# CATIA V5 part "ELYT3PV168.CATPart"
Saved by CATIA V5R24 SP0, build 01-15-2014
Part number: ELYT3PV168
Material "ZAMA": density 6700 kg/m3
Material "ZAMA": density 6700 kg/m3
Bounding box of the stored display mesh (mm): x -59 to 27.5, y 0 to 1680, z 0 to 1500
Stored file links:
  \\mnsrv021stg\Common\AREA TECNICA\Documenti\3D sito\Componenti risolti\ELYT3PV168.CATPart
  Z:\commesse\Novellini\Serie Zephiros\BH01S66\ID_18668_00.CATPart
  Z:\commesse\Novellini\Prove\Tabelladiprogetto1.txt
  Z:\commesse\Novellini\Prove\Tabelladiprogetto2.xls
  C:\Users\n.rebecchi\Desktop\Scambio\ID_35222_00.xls
  Z:\3D sito\BH02A.xlsx
  \\MNSRV021STG\Common\AREA TECNICA\Documenti\3D sito\BOX\ZEPHIROS\BH02A\BH02A.xls
  Z:\3D sito\ZEPHIROS\BH022P\BH022P.xls
  C:\Docisland\DocIsland\catia_workdir\diclient\N.REBECCHI\ID_21111_03.CATPart
  C:\Docisland\DocIsland\catia_workdir\diclient\N.REBECCHI\ID_29051_00.CATPart
  U:\AREA TECNICA\Documenti\3D sito\BOX\ZEPHYROS\ZEPHYR3P\BH013P.xls
  \\mnsrv021stg\Common\AREA TECNICA\Documenti\3D sito\BOX\ELYT\ZEPHYR3P\ELYT3PV.xls
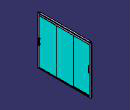
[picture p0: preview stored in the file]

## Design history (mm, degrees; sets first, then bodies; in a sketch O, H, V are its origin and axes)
Parameters
  `Larghezza anta` = 541 mm
  `MISURA NOMINALE` = 1680 mm
  PartNumber = "ELYT3PV168"
  `Lunghezza binario` = 1586 mm
Pad1: profile Sketch3.L13, length 1441, opposite side length -21
Solid1: solid without history
Solid2: solid without history
Pad2: profile Sketch3.L6, length 1441, opposite side length -21
Sketch1 on xy-plane, origin (0, 0, 0), H (1, 0, 0), V (0, 1, 0)
  axis line L1 (84.1025, 840) -> (-125.0839, 840)
  point P3 (-18.5, 0)
  point P4 (-18.5, 52.3)
  point P5 (0, 50.8)
  point P6 (-1.5, 52.3)
  point P8 (0, 1.5)
  point P9 (-1.5, 0)
  line L2 (0, 50.8) -> (0, 1.5)
  line L3 (-1.5, 0) -> (-32.75, 0)
  line L4 (-18.5, 1.5) -> (-18.5, 52.3)
  line L5 (-18.5, 52.3) -> (-1.5, 52.3)
  arc A1 centre (-1.5, 50.8) radius 1.5 from (0, 50.8) to (-1.5, 52.3) ccw
  arc A2 centre (-1.5, 1.5) radius 1.5 from (0, 1.5) to (-1.5, 0) cw
  line L6 (-18.5, 1.5) -> (-32.75, 1.5)
  point P11 (-32.75, 1.5)
  arc A3 centre (-32.75, 0.75) radius 0.75 from (-32.75, 1.5) to (-32.75, 0) ccw
  point P13 (-32.75, 0)
  point P14 (-18.5, 1.5)
  point P15 (-3, 1307.7)
  construction line L7 through (-1555.4, 0) direction (-1, 0)
  construction line L8 through (-1255.4, 0) direction (0, 1)
  point P16 (-18.5, 1680)
  point P17 (-18.5, 1627.7)
  point P18 (0, 1629.2)
  point P19 (-1.5, 1627.7)
  point P21 (0, 1678.5)
  point P22 (-1.5, 1680)
  point P24 (-32.75, 1678.5)
  point P26 (-32.75, 1680)
  point P27 (-18.5, 1678.5)
  line L9 (0, 1629.2) -> (0, 1678.5)
  line L10 (-1.5, 1680) -> (-32.75, 1680)
  line L11 (-18.5, 1678.5) -> (-18.5, 1629.1)
  line L12 (-52, 1627.7) -> (-1.5, 1627.7)
  arc A4 centre (-1.5, 1629.2) radius 1.5 from (0, 1629.2) to (-1.5, 1627.7) cw
  arc A5 centre (-1.5, 1678.5) radius 1.5 from (0, 1678.5) to (-1.5, 1680) ccw
  line L13 (-18.5, 1678.5) -> (-32.75, 1678.5)
  arc A6 centre (-32.75, 1679.25) radius 0.75 from (-32.75, 1678.5) to (-32.75, 1680) cw
  line L14 (-52, 1627.7) -> (-52, 1638.2)
  line L15 (-52, 1638.2) -> (-37, 1638.2)
  line L16 (-37, 1638.2) -> (-37, 1629.1)
  line L17 (-37, 1629.1) -> (-18.5, 1629.1)
  length L5 = 17
  radius A1 = 1.5
  distance L6 L3 = 1.5
  distance L4 A3 = 15
  distance L5 L3 = 52.3
  distance L2 L4 = 18.5
  radius A2 = 1.5
  distance L10 L3 = 1680 {= `MISURA NOMINALE`}
  distance L9 L14 = 52
  length L15 = 15
  distance L12 L17 = 1.4
  distance L15 L12 = 10.5
  tangency: A1 L2, A3 L3, A3 L6, L2 A2, A2 L3
  coincidence: P3 L3, P17 L11, P17 L12, L2 V, L3 L7, L3 H
  symmetry: P3 P16 L1, P4 P17 L1, P5 P18 L1, P6 P19 L1, P8 P21 L1, P9 P22 L1, P11 P24 L1, P13 P26 L1, P14 P27 L1, L2 L9 L1, L3 L10 L1, L4 L11 L1, L5 L12 L1, A1 A4 L1, A2 A5 L1, L6 L13 L1, A3 A6 L1
  vertical: L16 V
Pad3: profile Sketch1, direction (0, 0, 1), length 1500
Body1 "Telaio" (main body)
  Sketch2 on face of Pad3 from Sketch1.L5, origin (0, 52.3, 0), H (-1, 0, 0), V (0, 0, -1)
    point P1 (-1, -1500)
    line L1 (5.7859, -1500) -> (52.2221, -1500)
    line L2 (59, -1485.3692) -> (59, -1437.2118)
    construction line L3 (247.7599, -1440) -> (58, -1440)
    line L4 (-1, -1436.5) -> (-1, -1485.3692)
    point P2 (59, -1500)
    point P3 (59, -1440)
    construction line L5 (57.5, -1498) -> (57.5, -1486.5)
    construction line L6 (190.2599, -1498) -> (4.1139, -1498)
    point P5 (57.5, -1498)
    line L7 (57.7882, -1436) -> (-0.5, -1436)
    construction line L8 (8.597, -1485.5) -> (18.6226, -1485.5)
    construction line L9 (1.7786, -1486.5) -> (4.2562, -1486.5)
    construction line L10 (57.5, -1485.2) -> (57.5, -1440.5)
    construction line L11 (1, -1485) -> (1, -1464.277)
    point P6 (57.5, -1486.5)
    point P7 (1, -1485.5)
    construction line L12 (36.5779, -1495.9874) -> (36.5305, -1488.4874)
    construction line L13 (37.7781, -1496.0126) -> (37.7307, -1488.5126)
    construction line L14 (39.7307, -1486.5) -> (53.9552, -1486.5)
    construction line L15 (39.778, -1498) -> (50.7716, -1498)
    construction line L16 (18.9226, -1496) -> (18.9226, -1488.5)
    construction line L17 (20.1226, -1496) -> (20.1226, -1486.8)
    construction line L18 (20.4226, -1486.5) -> (34.5306, -1486.5)
    construction line L19 (22.1226, -1498) -> (34.5779, -1498)
    construction line L20 (18.9226, -1485.2) -> (18.9226, -1464.6071)
    construction line L21 (20.1226, -1485.2) -> (20.1226, -1466.4658)
    construction line L22 (36.5098, -1485.1981) -> (36.3815, -1464.8702)
    construction line L23 (37.7098, -1485.2019) -> (37.5963, -1467.2104)
    construction line L24 (20.4226, -1485.5) -> (222.4284, -1485.5)
    construction line L25 (38.0098, -1485.5) -> (57.2, -1485.5)
    construction line L26 (0.5, -1461.4168) -> (0.5, -1436.5)
    construction line L27 (46.4222, -1915.0185) -> (46.406, -1912.4534)
    construction line L28 (46.4222, -1915.0185) -> (47.9222, -1915.0091)
    construction arc A1 centre (8.7492, -1464.5115) radius 0.25 from (8.9992, -1464.5065) to (8.701, -1464.7568) cw
    construction arc A2 centre (5.7, -1465.25) radius 2.75 from (3.3803, -1463.773) to (8.3995, -1464.7254) cw
    point P12 (5.7, -1465.25)
    construction line L29 (1.4989, -1463.777) -> (3.3803, -1463.773)
    construction arc A3 centre (4.9238, -1464.5873) radius 4.0762 from (1.9856, -1461.762) to (9, -1464.5873) cw
    point P14 (8.9992, -1464.5065)
    construction arc A4 centre (8.7975, -1464.2662) radius 0.5 from (8.701, -1464.7568) to (8.321, -1464.4175) cw
    point P16 (8.321, -1464.4175)
    point P18 (23.1853, -1465.9683)
    point P19 (21.993, -1463.4903)
    point P20 (25.9312, -1465.8199)
    construction arc A5 centre (23.1853, -1465.9683) radius 2.75 from (21.993, -1463.4903) to (25.9123, -1465.6134) cw
    construction arc A6 centre (26.4305, -1465.7929) radius 0.5 from (25.9918, -1465.553) to (25.9312, -1465.8199) cw
    construction arc A7 centre (26.2112, -1465.6729) radius 0.25 from (26.45, -1465.7469) to (25.9918, -1465.553) cw
    construction arc A8 centre (23.4246, -1466.4658) radius 3.302 from (20.1226, -1466.4658) to (21.993, -1463.4903) cw
    point P24 (21.9929, -1463.4903)
    point P27 (40.6705, -1466.6867)
    construction arc A9 centre (43.6396, -1465.9948) radius 0.25 from (43.8765, -1466.0746) to (43.4818, -1466.1887) cw
    point P30 (43.3164, -1465.9372)
    construction arc A10 centre (43.7975, -1465.8009) radius 0.5 from (43.4818, -1466.1887) to (43.3164, -1465.9372) cw
    construction arc A11 centre (40.6705, -1466.6867) radius 2.75 from (39.5358, -1464.1817) to (43.3323, -1465.9959) cw
    construction arc A12 centre (40.8983, -1467.1895) radius 3.302 from (37.5963, -1467.2104) to (39.5358, -1464.1817) cw
    point P35 (211.7599, -1486.5)
    point P36 (12.6022, -1750.9456)
    point P37 (12.601, -1748.9456)
    point P38 (7.2208, -1496)
    point P39 (11.602, -1750.6462)
    point P40 (7.6073, -1494.5506)
    point P41 (7.6108, -1497.4484)
    point P42 (6.7699, -1497.6909)
    point P43 (5.9208, -1495.2516)
    point P44 (7.9723, -1497.2981)
    point P45 (5.9208, -1495.2516)
    point P46 (6.1845, -1494.2101)
    point P47 (7.9723, -1497.2981)
    point P48 (6.1845, -1494.2101)
    point P49 (6.7699, -1497.6909)
    point P50 (7.6073, -1494.5506)
    point P51 (7.6757, -1497.6898)
    point P52 (8.7353, -1495.1232)
    point P53 (5.9226, -1496.7516)
    point P54 (8.7353, -1495.1232)
    point P55 (5.9226, -1496.7516)
    point P56 (7.9692, -1494.7001)
    point P57 (7.9692, -1494.7001)
    point P58 (7.6108, -1497.4484)
    point P59 (7.6757, -1497.6898)
    construction arc A13 centre (7.2208, -1496) radius 1.5 from (7.6073, -1494.5506) to (7.6108, -1497.4484) ccw
    construction arc A14 centre (7.2208, -1496) radius 1.75 from (5.7042, -1495.1268) to (6.7699, -1497.6909) ccw
    construction line L30 (5.7042, -1495.1268) -> (5.9208, -1495.2516)
    construction arc A15 centre (7.2208, -1496) radius 1.5 from (7.9723, -1497.2981) to (5.9208, -1495.2516) ccw
    construction line L31 (6.1845, -1494.2101) -> (7.9723, -1497.2981)
    construction arc A16 centre (5.5354, -1494.5859) radius 0.75 from (6.1845, -1494.2101) to (5.5317, -1495.3359) ccw
    construction line L32 (6.7699, -1497.6909) -> (7.6073, -1494.5506)
    construction arc A17 centre (7.2208, -1496) radius 1.75 from (7.6757, -1497.6898) to (8.7353, -1495.1232) ccw
    construction line L33 (5.9226, -1496.7516) -> (8.7353, -1495.1232)
    construction arc A18 centre (7.2208, -1496) radius 1.5 from (5.9226, -1496.7516) to (7.9692, -1494.7001) ccw
    construction line L34 (7.9692, -1494.7001) -> (8.2527, -1494.2076)
    construction arc A19 centre (8.9027, -1494.5818) radius 0.75 from (9.4761, -1494.0984) to (8.2527, -1494.2076) ccw
    construction arc A20 centre (7.2208, -1496) radius 2.95 from (4.9609, -1494.1038) to (5.5608, -1493.5613) ccw
    construction line L35 (7.6108, -1497.4484) -> (7.6757, -1497.6898)
    point P60 (196.5645, -1917.6542)
    point P61 (11.6031, -1752.3962)
    point P62 (167.077, -1877.6984)
    construction line L36 (7.2208, -1496) -> (7.769, -1950.7895)
    point P63 (7.769, -1950.7895)
    construction line L37 (7.2208, -1496) -> (-0.9278, -1496)
    point P65 (4.9609, -1494.1038)
    point P67 (7.2232, -1498)
    construction line L38 (10.3276, -1498) -> (16.9226, -1498)
    construction arc A21 centre (4.1139, -1497.5) radius 0.5 from (4.5642, -1497.2826) to (4.1139, -1498) cw
    point P68 (4.5642, -1497.2826)
    construction arc A22 centre (7.2208, -1496) radius 2.95 from (9.4761, -1494.0984) to (9.8774, -1497.2826) cw
    construction arc A23 centre (10.3276, -1497.5) radius 0.5 from (9.8774, -1497.2826) to (10.3276, -1498) ccw
    point P74 (195.3181, -1910.0413)
    point P75 (197.3181, -1910.0413)
    point P77 (195.6181, -1911.0413)
    point P78 (193.8681, -1911.0413)
    point P79 (194.0428, -1910.0413)
    construction line L39 (198.7599, -1909.6171) -> (198.7599, -1904.8275)
    point P81 (196.7599, -1907.6171)
    construction line L40 (7.5212, -1762.7716) -> (7.5105, -1745.0224)
    point P85 (2.4259, -1750.9517)
    point P86 (2.4247, -1748.9517)
    point P88 (3.4257, -1750.6511)
    point P89 (3.4268, -1752.4011)
    point P90 (-151.896, -1877.8906)
    point P91 (7.5, -1950.7897)
    construction line L41 (7.5, -1935.9877) -> (7.5, -1950.7897)
    point P92 (7.5, -1497.9998)
    point P93 (2.4259, -1750.9517)
    point P94 (2.4247, -1748.9517)
    point P95 (7.5, -1487)
    point P96 (3.4257, -1750.6511)
    point P97 (7.8882, -1488.4489)
    point P98 (7.1118, -1488.4489)
    point P99 (7.9529, -1488.6904)
    point P100 (8.799, -1486.25)
    point P101 (8.25, -1485.701)
    point P102 (8.799, -1486.25)
    point P103 (8.5378, -1485.2025)
    point P104 (8.25, -1485.701)
    point P105 (8.5378, -1485.2025)
    point P106 (7.9529, -1488.6904)
    point P107 (7.8882, -1488.4489)
    point P108 (7.0471, -1488.6904)
    point P109 (5.9845, -1486.125)
    point P110 (6.201, -1486.25)
    point P111 (5.9845, -1486.125)
    point P112 (6.201, -1486.25)
    point P113 (6.75, -1485.701)
    point P114 (6.75, -1485.701)
    point P115 (7.1118, -1488.4489)
    point P116 (7.0471, -1488.6904)
    point P117 (3.4268, -1752.4011)
    point P118 (-151.896, -1877.8906)
    point P119 (7.5, -1950.7897)
    construction line L42 (7.5, -1487) -> (7.5, -1950.7897)
    point P120 (6.4659, -1485.2089)
    point P121 (7.5, -1497.9998)
    construction arc A24 centre (7.5, -1487) radius 1.5 from (7.8882, -1488.4489) to (7.1118, -1488.4489) cw
    construction arc A25 centre (7.5, -1487) radius 1.75 from (9.0155, -1486.125) to (7.9529, -1488.6904) cw
    construction line L43 (9.0155, -1486.125) -> (8.799, -1486.25)
    construction arc A26 centre (7.5, -1487) radius 1.5 from (8.25, -1485.701) to (8.799, -1486.25) cw
    construction line L44 (8.2506, -1485.7) -> (8.25, -1485.701)
    construction arc A27 centre (9.1873, -1485.5775) radius 0.75 from (8.5378, -1485.2025) to (9.6782, -1485.0105) cw
    construction line L45 (7.9529, -1488.6904) -> (7.8882, -1488.4489)
    construction arc A28 centre (7.5, -1487) radius 1.75 from (7.0471, -1488.6904) to (5.9845, -1486.125) cw
    construction line L46 (6.201, -1486.25) -> (5.9845, -1486.125)
    construction arc A29 centre (7.5, -1487) radius 1.5 from (6.201, -1486.25) to (6.75, -1485.701) cw
    construction line L47 (6.75, -1485.701) -> (6.7494, -1485.7)
    construction arc A30 centre (5.8164, -1485.5839) radius 0.75 from (5.2424, -1485.1011) to (6.4659, -1485.2089) cw
    construction arc A31 centre (7.5, -1487) radius 2.95 from (5.0963, -1485.2898) to (5.2424, -1485.1011) cw
    construction line L48 (7.1118, -1488.4489) -> (7.0471, -1488.6904)
    construction arc A32 centre (7.5, -1487) radius 2.95 from (4.5556, -1486.8185) to (10.45, -1487) ccw
    construction arc A33 centre (4.2562, -1486.8) radius 0.3 from (4.5556, -1486.8185) to (4.2562, -1486.5) ccw
    construction line L49 (16.9226, -1486.5) -> (10.95, -1486.5)
    construction arc A34 centre (10.95, -1487) radius 0.5 from (10.45, -1487) to (10.95, -1486.5) cw
    construction arc A35 centre (10.7882, -1483.9966) radius 1.5034 from (9.6782, -1485.0105) to (10.7882, -1485.5) ccw
    point P129 (9.6782, -1485.0105)
    point P130 (10.7882, -1485.5)
    construction line L50 (1.5, -1485.5) -> (6.403, -1485.5)
    construction arc A36 centre (4.6889, -1485) radius 0.5 from (5.0963, -1485.2898) to (4.6889, -1485.5) cw
    point P134 (4.6889, -1485.5)
    point P136 (9.6782, -1485.0105)
    construction arc A37 centre (6.403, -1485.9) radius 0.4 from (6.403, -1485.5) to (6.7494, -1485.7) cw
    construction arc A38 centre (8.597, -1485.9) radius 0.4 from (8.597, -1485.5) to (8.2506, -1485.7) ccw
    construction line L51 (191.961, -1463.0884) -> (240.5943, -1463.7586)
    construction line L52 (194.4697, -1470.2529) -> (261.0074, -1472.9865)
    construction circle A39 centre (7.2208, -1496) radius 1.75
    construction arc A40 centre (-0.5, -1499.5) radius 0.5 from (-1, -1499.5) to (-0.5, -1500) ccw
    point P147 (-1, -1499.5)
    point P148 (-0.5, -1500)
    construction arc A41 centre (58.5, -1499.5) radius 0.5 from (58.5, -1500) to (59, -1499.5) ccw
    point P150 (58.5, -1500)
    point P151 (59, -1499.5)
    arc A42 centre (-0.5, -1436.5) radius 0.5 from (-1, -1436.5) to (-0.5, -1436) cw
    construction arc A43 centre (0, -1436.5) radius 0.5 from (0, -1436) to (0.5, -1436.5) cw
    point P156 (0, -1436)
    construction arc A44 centre (58, -1440.5) radius 0.5 from (57.5, -1440.5) to (58, -1440) cw
    line L53 (-0.9205, -1485.76) -> (4.8654, -1499.3908)
    point P163 (-1, -1485.5727)
    arc A45 centre (5.7859, -1499) radius 1 from (4.8654, -1499.3908) to (5.7859, -1500) ccw
    point P164 (4.8654, -1499.3908)
    point P165 (5.7859, -1500)
    construction arc A46 centre (5.5292, -1495.8359) radius 0.5 from (5.5317, -1495.3359) to (5.0689, -1496.0313) cw
    construction arc A47 centre (1.7786, -1487) radius 0.5 from (1.3183, -1487.1954) to (1.7786, -1486.5) cw
    construction arc A48 centre (1.5, -1485) radius 0.5 from (1, -1485) to (1.5, -1485.5) ccw
    construction arc A49 centre (18.6226, -1485.2) radius 0.3 from (18.9226, -1485.2) to (18.6226, -1485.5) cw
    construction arc A50 centre (20.4226, -1485.2) radius 0.3 from (20.1226, -1485.2) to (20.4226, -1485.5) ccw
    construction arc A51 centre (16.9226, -1488.5) radius 2 from (16.9226, -1486.5) to (18.9226, -1488.5) cw
    construction line L54 (29, -1900.3555) -> (29, -1979.6079)
    point P187 (53.1346, -1499.3908)
    line L55 (58.9205, -1485.76) -> (53.1346, -1499.3908)
    arc A52 centre (52.2141, -1499) radius 1 from (53.1345, -1499.3908) to (52.2221, -1500) cw
    point P190 (59, -1485.5727)
    construction line L56 (55.7962, -1489.2815) -> (52.6126, -1496.7815)
    point P191 (-104.6902, -1867.3637)
    point P192 (-110.5556, -1881.1818)
    construction line L57 (59, -1485.5727) -> (-104.6902, -1867.3637)
    construction line L58 (53.1346, -1499.3908) -> (-110.5556, -1881.1818)
    construction line L59 (1.0011, -1461.9168) -> (1.6263, -1461.9155)
    construction arc A53 centre (1, -1461.4168) radius 0.5 from (0.5, -1461.4168) to (1.0011, -1461.9168) ccw
    construction arc A54 centre (1.6252, -1461.4155) radius 0.5 from (1.9856, -1461.762) to (1.6263, -1461.9155) cw
    construction arc A55 centre (22.7726, -1464.6071) radius 3.85 from (18.9226, -1464.6071) to (26.6226, -1464.6074) cw
    construction arc A56 centre (40.2297, -1464.8459) radius 3.8483 from (36.3815, -1464.8702) to (44.0779, -1464.8216) cw
    point P202 (40.2827, -1460.998)
    point P204 (43.8765, -1466.0746)
    point P205 (26.45, -1465.7469)
    arc A57 centre (0, -1485.3692) radius 1 from (-1, -1485.3692) to (-0.9205, -1485.76) ccw
    arc A58 centre (58, -1485.3692) radius 1 from (59, -1485.3692) to (58.9205, -1485.76) cw
    construction arc A59 centre (36.2098, -1485.2) radius 0.3 from (36.5098, -1485.1981) to (36.2098, -1485.5) cw
    construction arc A60 centre (38.0098, -1485.2) radius 0.3 from (37.7098, -1485.2019) to (38.0098, -1485.5) ccw
    construction arc A61 centre (39.7307, -1488.5) radius 2 from (37.7307, -1488.5126) to (39.7307, -1486.5) cw
    construction arc A62 centre (34.5306, -1488.5) radius 2 from (34.5306, -1486.5) to (36.5305, -1488.4874) cw
    construction arc A63 centre (34.5779, -1496) radius 2 from (36.5779, -1495.9874) to (34.5779, -1498) cw
    construction arc A64 centre (39.778, -1496) radius 2 from (37.7781, -1496.0126) to (39.778, -1498) ccw
    construction arc A65 centre (22.1226, -1496) radius 2 from (20.1226, -1496) to (22.1226, -1498) ccw
    construction arc A66 centre (16.9226, -1496) radius 2 from (18.9226, -1496) to (16.9226, -1498) cw
    construction arc A67 centre (50.7716, -1496) radius 2 from (52.6126, -1496.7815) to (50.7716, -1498) cw
    construction arc A68 centre (57.2, -1485.2) radius 0.3 from (57.5, -1485.2) to (57.2, -1485.5) cw
    construction arc A69 centre (1.5, -1464.277) radius 0.5 from (1, -1464.277) to (1.4989, -1463.777) cw
    construction arc A70 centre (53.9552, -1488.5) radius 2 from (53.9552, -1486.5) to (55.7962, -1489.2815) cw
    construction line L60 (1.3183, -1487.1954) -> (5.0689, -1496.0313)
    point P247 (162.3117, -1866.472)
    point P248 (168.0976, -1880.1028)
    construction line L61 (-0.9205, -1485.76) -> (162.3117, -1866.472)
    construction line L62 (4.8654, -1499.3908) -> (168.0976, -1880.1028)
    construction line L63 (57.3536, -1460.1464) -> (55.6464, -1461.8536)
    point P251 (57.5, -1460)
    construction line L64 (55.5, -1462.2071) -> (55.5, -1485)
    point P252 (55.5, -1485.5)
    construction arc A71 centre (55, -1485) radius 0.5 from (55.5, -1485) to (55, -1485.5) cw
    point P254 (55, -1485.5)
    construction arc A72 centre (56, -1462.2071) radius 0.5 from (55.5, -1462.2071) to (55.6464, -1461.8536) cw
    construction arc A73 centre (57, -1459.7929) radius 0.5 from (57.5, -1459.7929) to (57.3536, -1460.1464) cw
    point P259 (57.5, -1459.7929)
    construction line L65 (9, -1464.5873) -> (9, -1465.2632)
    construction arc A74 centre (8.7, -1465.2632) radius 0.3 from (9, -1465.2632) to (8.4, -1465.2632) cw
    construction line L66 (8.3995, -1464.7254) -> (8.4, -1465.2632)
    axis line L67 (204.6582, -1469.5884) -> (238.7986, -1470.2896)
    construction line L68 (26.6226, -1464.6074) -> (26.6225, -1465.5674)
    construction arc A75 centre (26.2659, -1465.5674) radius 0.3566 from (25.9123, -1465.6134) to (26.6225, -1465.5674) ccw
    construction line L69 (44.0779, -1464.8216) -> (44.0847, -1465.8974)
    construction arc A76 centre (43.7024, -1465.8999) radius 0.3823 from (43.3323, -1465.9959) to (44.0847, -1465.8974) ccw
    point P279 (213.6284, -1912.5175)
    point P280 (222.8519, -1905.6947)
    point P281 (220.8519, -1903.6947)
    point P282 (222.4284, -1485.5)
    point P283 (222.4284, -1485.5)
    construction line L70 (222.4284, -1485.5) -> (36.2098, -1485.5)
    construction arc A77 centre (20.4226, -1486.8) radius 0.3 from (20.1226, -1486.8) to (20.4226, -1486.5) cw
    arc A78 centre (57.7882, -1437.2118) radius 1.2118 from (57.7882, -1436) to (59, -1437.2118) cw
    point P290 (0, 0)
    point P291 (0, 0)
    point P304 (0.6, -33)
    line L71 (0.5, 0) -> (48.5, 0)
    line L72 (50, -1.5) -> (50, -11.2929)
    line L73 (0, -17.5) -> (48.1743, -13.2853)
    line L74 (-0.5, -35) -> (0.0954, -35)
    line L75 (-1, -34.5) -> (-1, -1.5)
    arc A79 centre (0.5, -1.5) radius 1.5 from (-1, -1.5) to (0.5, 0) cw
    line L76 (0, -32.0835) -> (0, -17.5)
    arc A80 centre (-0.5, -34.5) radius 0.5 from (-1, -34.5) to (-0.5, -35) ccw
    arc A81 centre (48, -11.2929) radius 2 from (48.1743, -13.2853) to (50, -11.2929) ccw
    line L77 (0.6, -34.4954) -> (0.6, -33)
    arc A82 centre (0.0954, -34.4954) radius 0.5046 from (0.0954, -35) to (0.6, -34.4954) ccw
    arc A83 centre (0.1, -33) radius 0.5 from (0.3, -32.5417) to (0.6, -33) cw
    arc A84 centre (0.5, -32.0835) radius 0.5 from (0.3, -32.5417) to (0, -32.0835) cw
    arc A85 centre (48.5, -1.5) radius 1.5 from (50, -1.5) to (48.5, 0) ccw
    reference intersected line E1 through (0, 0) direction (0, -1) from face of Pad3 from Sketch1.L2
    reference intersected line E2 (18.5, -1500) -> (1.5, -1500) from end face of Pad3
    point P312 (0, -17.5)
    distance L2 L5 = 1.5
    distance L1 L6 = 2
    distance L8 L9 = 1
    distance L20 L21 = 1.2
    distance L22 L23 = 1.2
    distance L11 L20 = 17.9226 (reference)
    distance L23 L27 = 6
    radius A1 = 0.25
    radius A2 = 2.75
    distance L11 P12 = 4.7 (reference)
    radius A4 = 0.5
    radius A7 = 0.25
    radius A6 = 0.5
    radius A5 = 2.75
    radius A11 = 2.75
    radius A9 = 0.25
    radius A10 = 0.5
    radius A14 = 1.75
    distance A14 A15 = 0.25
    radius A13 = 1.5
    radius A20 = 2.95
    angle L31 L36 = 330
    angle L34 L31 = 60
    angle L30 L31 = 30
    angle L32 L35 = 30
    angle L35 L33 = 105
    radius A19 = 0.75
    radius A16 = 0.75
    angle L34 L33 = 30
    angle L31 L30 = 30 (reference)
    radius A21 = 0.5
    radius A23 = 0.5
    distance P38 P95 = 9
    radius A33 = 0.3
    radius A34 = 0.5
    radius A35 = 1.5034
    radius A28 = 1.75
    radius A32 = 2.95
    radius A29 = 1.5
    radius A36 = 0.5
    angle L47 L44 = 60
    radius A30 = 0.75
    angle L44 L43 = 30
    radius A27 = 0.75
    angle L42 L48 = 15
    radius A37 = 0.4
    radius A38 = 0.4
    distance P12 L50 = 20.25
    distance L29 P12 = 1.482
    distance A3 L29 = 3.2585
    distance L29 A1 = 1
    distance P18 P27 = 17.5
    radius A12 = 3.302
    radius A8 = 3.302
    radius A3 = 4.0762
    distance A3 P12 V = 3.4134 (reference)
    distance P18 P12 = 17.5
    distance L1 P38 = 4
    radius A40 = 0.5
    distance P2 P3 = 60
    radius A41 = 0.5
    radius A42 = 0.5
    radius A43 = 0.5
    radius A44 = 0.5
    distance L4 P95 = 8.5
    radius A45 = 1
    angle L53 L4 = 157
    distance L4 P165 = 6.7859
    distance P163 L1 = 14.4273 (reference)
    radius A46 = 0.5
    radius A47 = 0.5
    radius A48 = 0.5
    distance L22 P27 = 4.2774
    radius A49 = 0.3
    radius A50 = 0.3
    radius A51 = 2
    distance L4 L26 = 1.5
    length L4 = 48.8692 (reference)
    distance L55 L56 = 1.5
    radius A53 = 0.5
    radius A54 = 0.5
    distance L29 L59 = 1.8612
    distance L11 L4 = 2
    distance L20 A55 = 7.7
    radius A9 = 0.25 (reference)
    distance L22 L69 = 7.6965
    radius A57 = 1
    radius A58 = 1
    radius A59 = 0.3
    radius A60 = 0.3
    radius A61 = 2
    radius A62 = 2
    radius A63 = 2
    radius A64 = 2
    radius A65 = 2
    radius A66 = 2
    radius A67 = 2
    radius A68 = 0.3
    radius A69 = 0.5
    radius A70 = 2
    distance L53 L60 = 1.5
    distance L16 L17 = 1.2 (reference)
    distance L20 L16 = 0
    distance L21 L17 = 0
    distance L22 L12 = 0
    distance L13 L23 = 0
    distance L12 L13 = 1.2 (reference)
    distance L1 L25 = 14.5
    distance P251 L3 = 20
    distance L2 L64 = 3.5
    angle L63 L10 = 135
    radius A71 = 0.5
    radius A72 = 0.5
    radius A73 = 0.5
    radius A74 = 0.3
    distance A74 L51 = 5
    distance L11 L65 = 8 (reference)
    radius A75 = 0.3566 (reference)
    radius A76 = 0.3823 (reference)
    distance L20 L65 = 9.9226
    distance L65 P12 = 3.3
    distance L4 P12 = 6.7
    distance L1 L7 = 64
    radius A77 = 0.3
    radius A78 = 1.2118
    distance L1 H = 1500 (reference)
    distance L71 L74 = 35
    distance L75 E1 = 1
    distance L75 L72 = 51
    distance L75 L76 = 1
    radius A85 = 1.5
    radius A81 = 2
    radius A80 = 0.5
    radius A82 = 0.5046
    distance L75 L77 = 1.6
    radius A83 = 0.5
    radius A84 = 0.5
    radius A79 = 1.5
    distance L2 L4 = 60
    angle L71 L73 = 5
    distance L71 P312 = 17.5
    distance L74 P304 = 2
    coincidence: L5 L10, L9 L14, L6 L15, L9 L18, L6 L19, L8 L24, L24 L25, A8 P24, P24 A5, A8 P19, P19 A5, A14 A17, A13 A15, A18 A13, L34 P38, L31 P38, P47 P44, P43 P45, P59 P51, P49 P42, L32 P38, L35 P38, L33 P38, P53 P55, P54 P52, P57 P56, P48 P46, L30 P38, P41 P58, P40 L32, L6 L38, L36 P67, L6 P67, L38 P67, P102 P100, P104 P101, P105 P103, P106 P99, P107 P97, P111 P109, P112 P110, P114 P113, P115 P98, P116 P108, L9 P35, L8 P7, A28 A25, A26 A24, A29 A26, P129 A31, P136 P129, A31 A32, L44 P95, L43 P95, L48 P95, L50 P134, L47 P120, L8 P130, L44 P103, L8 L50, L4 P1, L1 P1, L1 P2, L2 P2, L3 P3, L2 P3, P147 L4, P148 L1, A20 P68, A16 P65, L11 P7, L50 P7, L49 P35, P150 L1, P151 L2, P192 L56, P5 L15, P191 L56, P6 L14, A56 P202, P202 L51, L4 P163, L53 P163, L2 P190, L55 P190, L60 P62, P247 L60, P248 L60, P251 L10, P252 L25, P251 L63, L64 P252, P14 A3, P16 A2, A5 P20, P205 A55, A11 P30, P204 A56, P259 L10, P254 L25, L24 P282, L24 L70, P283 P282, L7 P156, P50 P40, L71 H, L4 L75, L1 E2
    tangency: A3 A1, A4 A1, A2 A4, A5 A6, A6 A7, A11 A10, A10 A9, A19 L34, A16 L31, A19 A20, A16 A20, A21 L6, A21 A20, A22 A16, A23 A22, A23 L38, A33 A32, A33 L9, L49 A33, A34 A32, A34 L49, A35 A31, A35 L8, L50 A24, A36 A31, A36 L50, L44 A27, L47 A30, A31 A30, A37 L50, A37 L47, A38 L8, A38 L44, L51 A3, L52 A2, L52 A5, A11 L52, A8 A5, A11 A12, A8 L21, A12 L23, A40 L4, A40 L1, A41 L1, A41 L2, A42 L4, A42 L7, A43 L7, A43 L26, A44 L10, A44 L3, A45 L53, A45 L1, A46 A16, A47 L9, A48 L11, A48 L50, A49 L20, A49 L8, A50 L21, A50 L24, A51 L49, A51 L16, A53 L26, A53 L59, A54 L59, A54 A3, A55 L51, L20 A55, A55 A7, A56 L22, A56 L51, A9 A56, A57 L4, A57 L53, A58 L2, A58 L55, A59 L22, A59 L24, A60 L23, A60 L25, A61 L13, A61 L14, A62 L18, A62 L12, A63 L12, A63 L19, A64 L13, A64 L15, A65 L17, A65 L19, A66 L16, A66 L38, A67 L56, A67 L15, A68 L10, A68 L25, A69 L11, A69 L29, A70 L14, A70 L56, A47 L60, A46 L60, A71 L64, A71 L25, A72 L64, A72 L63, A73 L10, A73 L63, L65 A3, L66 A74, L65 A74, L67 A74, A7 L67, L68 A55, A75 L68, A75 A5, A75 L67, L69 A56, A76 L69, A76 A11, L67 A76, A77 L17, A77 L18, A78 L7, A78 L2, L71 A85, L72 A85, L72 A81, A81 L73, A84 L76, L77 A83, L71 A79, L75 A79, A83 A84
    concentricity: A17 A14, A14 P38, P38 A39, A20 A14, A32 A28, A28 P95, A26 A24, A29 A28
    symmetry: P36 P85 L40, P37 P86 L40, P39 P88 L40, P61 P89 L40, P62 P90 L40, P63 P91 L40, L36 L41 L40, P67 P92 L40, P36 P93 L40, P37 P94 L40, P39 P96 L40, P61 P117 L40, P62 P118 L40, P63 P119 L40, L36 L42 L40, P67 P121 L40, L47 L44 L42, L46 L43 L42, L48 L45 L42, L4 L2 L54, P164 P187 L54, L53 L55 L54, A45 A52 L54
  Pad4: profile Sketch2, direction (0, 1, 0), up to face of Pad3 from Sketch1.L12
Body2 "Maniglia sx"
Body3 "Vetro sx"
Body4 "maniglia dx"
Body5 "Vetro centrale"
  Pad5: profile Sketch3.L2, length 1441, opposite side length -21
  Sketch3 on xy-plane, origin (0, 0, 0), H (1, 0, 0), V (0, 1, 0)
    point P1 (-22, 627.7)
    line L1 (-19, 569.0303) -> (-24.9999, 568.9985)
    line L2 (-25, 568.9985) -> (-25, 1109.9985)
    line L3 (-25, 1109.9985) -> (-19, 1109.9978)
    line L4 (-19, 1109.9978) -> (-19, 569.0303)
    point P6 (-39.5, 1357.2002)
    line L5 (-36.5, 1086.7) -> (-42.5, 1086.7008)
    line L6 (-42.5, 1086.7008) -> (-42.5, 1627.7)
    line L7 (-42.5, 1627.7) -> (-36.5, 1627.7)
    line L8 (-36.5, 1627.7) -> (-36.5, 1086.7)
    construction line L9 (-39.5, 1357.2002) -> (-39.5, -213.0288)
    point P12 (-4.5, 321.9136)
    line L10 (-1.5, 51.4234) -> (-7.5, 51.4235)
    line L11 (-7.5, 51.4235) -> (-7.5, 592.3916)
    line L12 (-7.5, 592.3916) -> (-1.5, 592.4234)
    line L13 (-1.5, 592.4234) -> (-1.5, 51.4234)
    construction line L14 (-4.5, 321.9136) -> (-122.8046, 321.9136)
    point P18 (4, -1)
    point P19 (4, 1038.4)
    axis line L15 (-22, 627.7) -> (-154.4866, 627.7)
    reference projected line E1 (-1.5, 1627.7) -> (-48.1743, 1627.7) from edge [face of Pad3 from Sketch1.L12 | face of Pad4 from Sketch2.L73]
    length L2 = 541 {= `Larghezza anta`}
    length L8 = 541 {= `Larghezza anta`}
    length L1 = 6
    length L5 = 6
    length L10 = 6
    length L13 = 541 {= `Larghezza anta`}
    distance L13 L4 = 17.5
    distance L8 L4 = 17.5
    distance L3 L5 = 23.3
    distance L12 L1 = 23.3
    distance L13 V = 1.5
    distance L11 L13 = 6
    distance L4 L2 = 6
    distance L6 L8 = 6
    distance L7 E1 = 0
    equidistance: L2 L4 P1, L5 L7 P6, L6 L8 P6, L10 L12 P12, L11 L13 P12
    vertical: L9 V
Body6 "Vetro dx"
Relations
  Value = `Larghezza anta`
